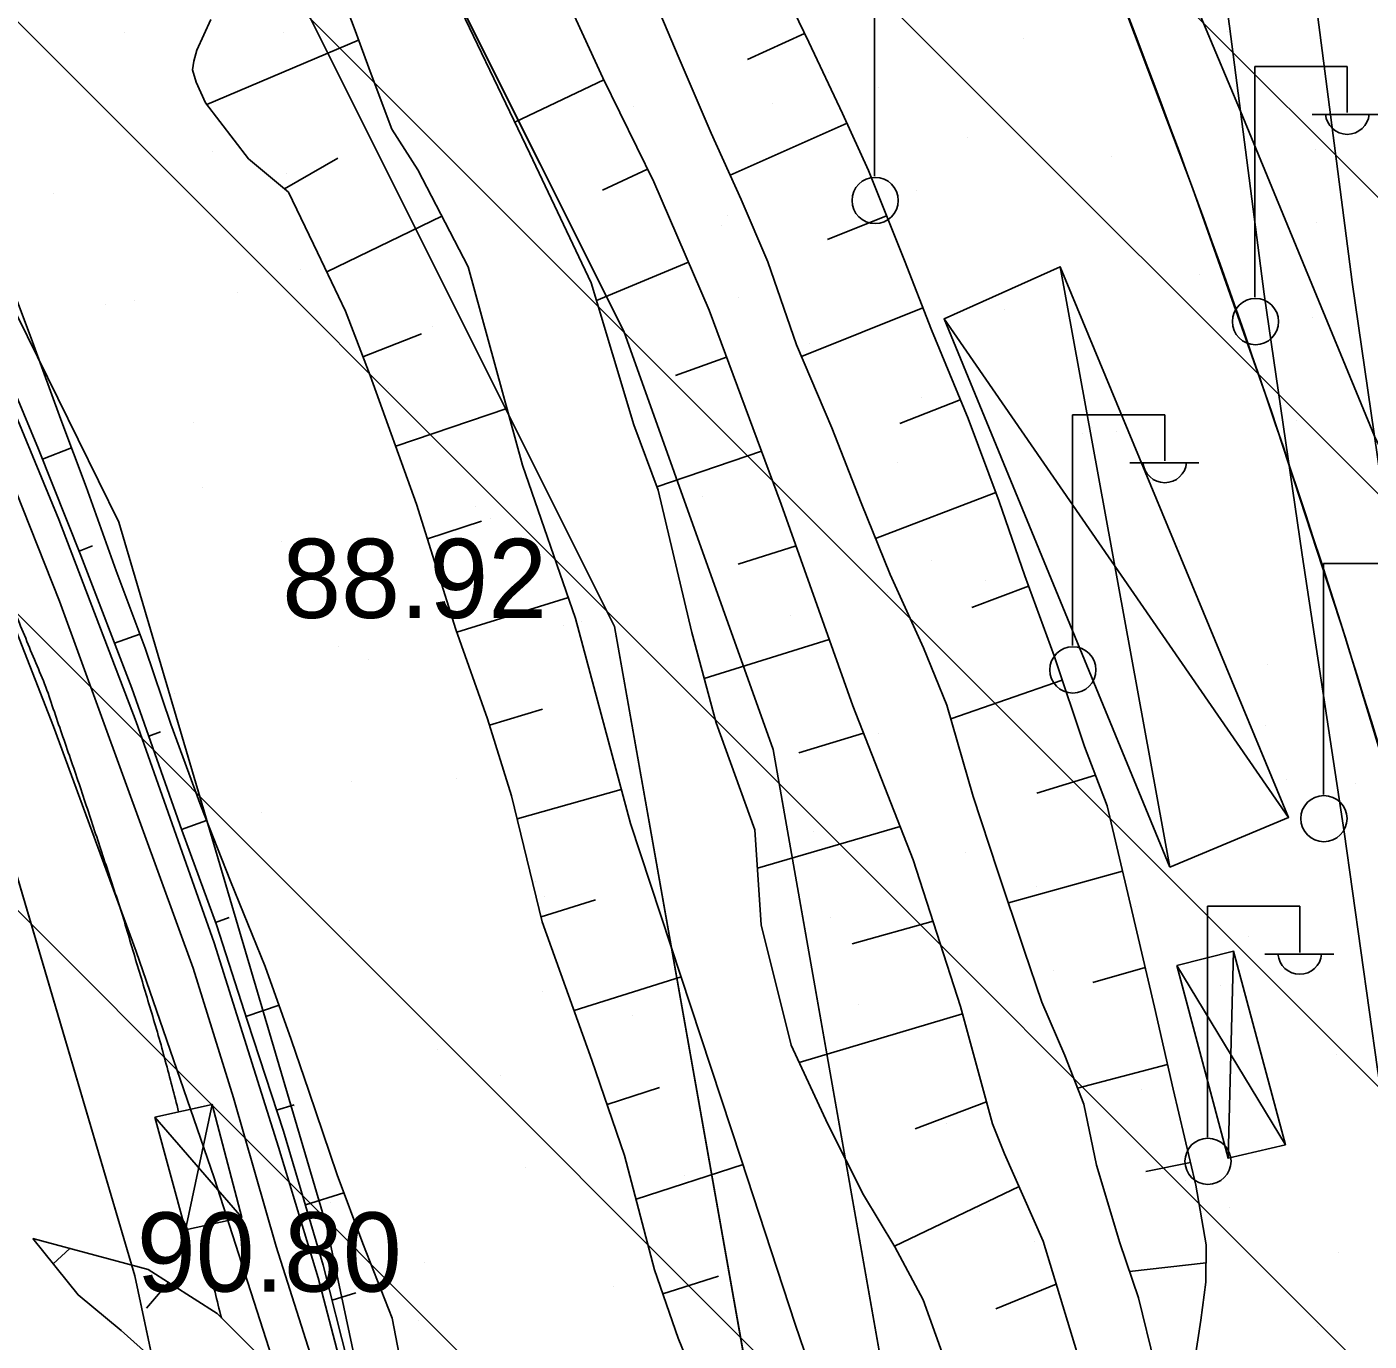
# Model space of a CAD drawing. Extents: x 417995 to 421451, y 4454518 to 4458015.
# Drawn here: x 421106.9 to 421208.7, y 4455902 to 4456001.6 of the extents above; entities that cross this region are included whole.
import ezdxf

# ---------------------------------------------------------------- set-up
doc = ezdxf.new("R2010")
doc.units = 0
for name, color, linetype in [('ADAKENARI', 7, 'Continuous'), ('B_Sundurma', 7, 'Continuous'), ('Default', 7, 'Continuous'), ('Egri_1m', 7, 'Continuous'), ('Hid_Dere_Sulu_Yat_Gen', 7, 'Continuous'), ('PL_AYA_BOLGE_PARKI', 7, 'Continuous'), ('PL_AYA_PARK_DINLENME', 7, 'Continuous'), ('PL_T_GUNUBIRLIK', 7, 'Continuous'), ('PL_TA_K_DERE', 7, 'Continuous'), ('S_Elektrik_Diregi', 7, 'Continuous'), ('Sev_Sevalti', 7, 'Continuous'), ('Sev_Sevustu', 7, 'Continuous'), ('Sev_Tarama', 7, 'Continuous'), ('Sinir_Tel_bir_taraf', 7, 'Continuous'), ('SN_TR_SIVILASMA', 7, 'Continuous'), ('TR_PARKALANI', 7, 'Continuous'), ('Y_Kot_Noktasi', 7, 'Continuous'), ('Y_Yol_Kotu', 7, 'Continuous'), ('Yol_Sose', 7, 'Continuous'), ('Yol_Toprak_Duz', 7, 'Continuous'), ('Yol_Toprak_Kesik', 7, 'Continuous')]:
    doc.layers.add(name, color=color, linetype=linetype)

# ---------------------------------------------------------------- blocks, each defined once
blk = doc.blocks.new('POINT_DISPLAY')
at = {"layer": 'Default'}
blk.add_line((0, 0), (0, 0), dxfattribs=at)

msp = doc.modelspace()

# ---------------------------------------------------------------- linework, layer by layer
at = {"layer": 'ADAKENARI'}
for p, q in [((421123.49, 4456035.93), (421152.17, 4455978.57)), ((421113.88, 4455964.09), (421080.66, 4456031.58)), ((421151.46, 4455956.18), (421128.16, 4456002.78)), ((421152.17, 4455978.57), (421163.49, 4455946.88)), ((421129.66, 4455910.66), (421113.88, 4455964.09)), ((421115.11, 4455906.97), (421099.86, 4455958.61)), ((421161.71, 4455898.39), (421151.46, 4455956.18)), ((421163.49, 4455946.88), (421172.54, 4455895.56)), ((421141.07, 4455857.05), (421129.66, 4455910.66)), ((421126.3, 4455854.38), (421115.11, 4455906.97))]:
    msp.add_line(p, q, dxfattribs=at)
msp.add_arc((420434.01, 4455711.76), 810.32, 14.95584, 31.47684, dxfattribs=at)
at = {"layer": 'B_Sundurma'}
for p, q in [((421193.56, 4455937.95), (421185.24, 4455983.45)), ((421202.55, 4455941.72), (421176.44, 4455979.5)), ((421198.38, 4455931.58), (421197.97, 4455915.89)), ((421194.09, 4455930.51), (421202.31, 4455916.92)), ((421118.95, 4455910.46), (421120.96, 4455919.97)), ((421116.61, 4455919), (421123.21, 4455911.4))]:
    msp.add_line(p, q, dxfattribs=at)
for points in [[(421193.56, 4455937.95), (421202.55, 4455941.72), (421185.24, 4455983.45), (421176.44, 4455979.5)], [(421193.56, 4455937.95), (421176.44, 4455979.5), (421185.24, 4455983.45), (421202.55, 4455941.72)], [(421194.09, 4455930.51), (421198.38, 4455931.58), (421202.31, 4455916.92), (421197.97, 4455915.89)], [(421194.09, 4455930.51), (421198.38, 4455931.58), (421202.31, 4455916.92), (421197.97, 4455915.89)], [(421116.61, 4455919), (421118.95, 4455910.46), (421123.21, 4455911.4), (421120.96, 4455919.97)], [(421116.61, 4455919), (421120.96, 4455919.97), (421123.21, 4455911.4), (421118.95, 4455910.46)]]:
    msp.add_lwpolyline(points, close=True, dxfattribs=at)
at = {"layer": 'Egri_1m'}
for points in [[(421118.42, 4455919.4), (421117.92, 4455921.34), (421117.41, 4455923.27), (421116.88, 4455925.2), (421116.31, 4455927.12), (421115.74, 4455929.03), (421115.16, 4455930.95), (421114.59, 4455932.87), (421114.01, 4455934.78), (421113.38, 4455936.68), (421112.76, 4455938.58), (421112.13, 4455940.48), (421111.5, 4455942.38), (421110.87, 4455944.28), (421110.22, 4455946.17), (421109.57, 4455948.06), (421108.92, 4455949.95), (421108.26, 4455951.84), (421107.49, 4455953.68), (421106.73, 4455955.53), (421105.96, 4455957.38), (421105.17, 4455959.22), (421104.86, 4455959.86)], [(421121.66, 4455903.8), (421121.18, 4455905.74), (421120.76, 4455907.7), (421120.48, 4455909.68), (421120.33, 4455910.77)]]:
    msp.add_spline(points, degree=3, dxfattribs=at)
at = {"layer": 'Hid_Dere_Sulu_Yat_Gen'}
for points in [[(421168.02, 4455894.88), (421165.15, 4455903.32), (421161.07, 4455915.83), (421152.67, 4455941.25), (421148.51, 4455956.81), (421144.48, 4455968.43), (421140.37, 4455983.45), (421136.54, 4455990.8), (421134.58, 4455993.87), (421133, 4455998.04), (421131.72, 4456001.56), (421127.14, 4456013.61)], [(421176.77, 4455899.81), (421174.85, 4455905.16), (421172.71, 4455909.18), (421170.32, 4455913.12), (421167.63, 4455918.48), (421164.85, 4455924.47), (421162.57, 4455933.58), (421162.1, 4455940.78), (421159.16, 4455948.89), (421157.32, 4455955.73), (421154.76, 4455966.53), (421152.91, 4455971.48), (421149.7, 4455982.23), (421145.03, 4455992.04), (421138.34, 4456006)]]:
    msp.add_lwpolyline(points, dxfattribs=at)
at = {"layer": 'PL_AYA_BOLGE_PARKI'}
msp.add_arc((420434.01, 4455711.76), 810.32, 14.95584, 31.47684, dxfattribs=at)
at = {"layer": 'PL_AYA_PARK_DINLENME'}
for points in [[(421180.89, 4455533.26), (421185.37, 4455543.12), (421189.15, 4455562.75), (421185.37, 4455581.61), (421187.64, 4455605.76), (421201.22, 4455660.85), (421206.51, 4455675.19), (421201.98, 4455705.38), (421192.17, 4455724.25), (421183.86, 4455734.81), (421185.37, 4455754.43), (421195.18, 4455786.88), (421198.96, 4455811.79), (421197.45, 4455846.5), (421189.15, 4455863.11), (421172.54, 4455895.56), (421163.49, 4455946.88), (421152.17, 4455978.57), (421123.49, 4456035.93)], [(421164.19, 4455706.15), (421157.68, 4455755.43), (421157.68, 4455755.42), (421155.11, 4455773.39), (421152.17, 4455791.3), (421148.85, 4455809.15), (421145.15, 4455826.92), (421141.09, 4455844.61), (421136.64, 4455862.22), (421131.83, 4455879.72), (421126.66, 4455897.12), (421121.11, 4455914.4), (421115.21, 4455931.57), (421108.94, 4455948.61), (421102.32, 4455965.51), (421095.34, 4455982.27), (421088.01, 4455998.87), (421080.33, 4456015.32)], [(421188.93, 4456006.25), (421195.28, 4455989.43), (421201.25, 4455972.48), (421206.84, 4455955.4), (421212.06, 4455938.2), (421216.89, 4455920.89), (421236.23, 4455848.47), (421240.3, 4455832.49), (421243.98, 4455816.42), (421247.29, 4455800.26), (421250.21, 4455784.03), (421252.74, 4455767.74), (421254.89, 4455751.39), (421256.64, 4455734.99), (421258.01, 4455718.56), (421258.99, 4455702.09)], [(421128.16, 4456002.78), (421151.46, 4455956.18), (421161.71, 4455898.39), (421179.42, 4455840.61), (421181.6, 4455782.36), (421174.05, 4455744.62), (421174.05, 4455720.47), (421186.88, 4455697.83), (421195.18, 4455678.97), (421186.13, 4455648.78), (421172.54, 4455608.78), (421170.28, 4455589.91), (421180.09, 4455564.26), (421178.58, 4455549.16), (421174.81, 4455545.39), (421170.82, 4455538.15)]]:
    msp.add_lwpolyline(points, dxfattribs=at)
at = {"layer": 'PL_T_GUNUBIRLIK'}
msp.add_lwpolyline([(421067.57, 4456024.2), (421099.86, 4455958.61), (421115.11, 4455906.97), (421126.3, 4455854.38), (421133.7, 4455804.79), (421152.1, 4455679.21), (421144.29, 4455586.77), (421139.27, 4455582.57), (421022.63, 4455660.74)], dxfattribs=at)
at = {"layer": 'PL_TA_K_DERE'}
for points in [[(421180.98, 4455533.46), (421185.37, 4455543.12), (421189.15, 4455562.75), (421185.37, 4455581.61), (421187.64, 4455605.76), (421201.22, 4455660.85), (421206.51, 4455675.19), (421201.98, 4455705.38), (421192.17, 4455724.25), (421183.86, 4455734.81), (421185.37, 4455754.43), (421195.18, 4455786.88), (421198.96, 4455811.79), (421197.45, 4455846.5), (421189.15, 4455863.11), (421172.54, 4455895.56), (421163.49, 4455946.88), (421152.17, 4455978.57), (421123.49, 4456035.93)], [(421128.16, 4456002.78), (421151.46, 4455956.18), (421161.71, 4455898.39), (421179.42, 4455840.61), (421181.6, 4455782.36), (421174.05, 4455744.62), (421174.05, 4455720.47), (421186.88, 4455697.83), (421195.18, 4455678.97), (421186.13, 4455648.78), (421172.54, 4455608.78), (421170.28, 4455589.91), (421180.09, 4455564.26), (421178.58, 4455549.16), (421174.81, 4455545.39), (421170.94, 4455538.38)]]:
    msp.add_lwpolyline(points, dxfattribs=at)
at = {"layer": 'S_Elektrik_Diregi'}
for p, q in [((421171.17, 4455990.32), (421171.17, 4456007.82)), ((421200, 4455981.14), (421200, 4455998.64)), ((421200, 4455998.64), (421207, 4455998.64)), ((421207, 4455995.14), (421207, 4455998.64)), ((421204.34, 4455995), (421209.59, 4455995)), ((421186.17, 4455954.74), (421186.17, 4455972.24)), ((421186.17, 4455972.24), (421193.17, 4455972.24)), ((421193.17, 4455968.74), (421193.17, 4455972.24)), ((421190.51, 4455968.6), (421195.76, 4455968.6)), ((421205.19, 4455943.46), (421205.19, 4455960.96)), ((421205.19, 4455960.96), (421212.19, 4455960.96)), ((421196.4, 4455917.49), (421196.4, 4455934.99)), ((421196.4, 4455934.99), (421203.4, 4455934.99)), ((421203.4, 4455931.49), (421203.4, 4455934.99)), ((421200.74, 4455931.35), (421205.99, 4455931.35))]:
    msp.add_line(p, q, dxfattribs=at)
for centre in [(421171.21, 4455988.48), (421200.04, 4455979.3), (421186.2, 4455952.9), (421205.23, 4455941.63), (421196.44, 4455915.66)]:
    msp.add_circle(centre, 1.75, dxfattribs=at)
for centre in [(421207, 4455995.15), (421193.17, 4455968.75), (421203.4, 4455931.5)]:
    msp.add_arc(centre, 1.66, 184.8384, 355.1464, dxfattribs=at)
at = {"layer": 'Sev_Sevalti'}
for points in [[(421168.02, 4455894.88), (421165.15, 4455903.32), (421161.07, 4455915.83), (421152.67, 4455941.25), (421148.51, 4455956.81), (421144.48, 4455968.43), (421140.37, 4455983.45), (421136.54, 4455990.8), (421134.58, 4455993.87), (421133, 4455998.04), (421131.72, 4456001.56), (421127.14, 4456013.61)], [(421094.71, 4456007.22), (421097.85, 4456000.22), (421100.28, 4455994.8), (421102.87, 4455988.66), (421105.09, 4455983.78), (421107.35, 4455977.77), (421109.5, 4455971.87), (421111.42, 4455966.77), (421113.69, 4455960.42), (421115.87, 4455954.56), (421117.84, 4455948.79), (421120.09, 4455942.6), (421122.34, 4455936.88), (421124.99, 4455930.42), (421126.95, 4455924.88), (421128.3, 4455920.97), (421130.44, 4455914.63), (421132.38, 4455909.42), (421134.61, 4455903.77), (421135.51, 4455899.04), (421136.14, 4455895.18), (421133.11, 4455892.83)], [(421176.77, 4455899.81), (421174.85, 4455905.16), (421172.71, 4455909.18), (421170.32, 4455913.12), (421167.63, 4455918.48), (421164.85, 4455924.47), (421162.57, 4455933.58), (421162.1, 4455940.78), (421159.16, 4455948.89), (421157.32, 4455955.73), (421154.76, 4455966.53), (421152.91, 4455971.48), (421149.7, 4455982.23), (421145.03, 4455992.04), (421138.34, 4456006)], [(421154.07, 4456004.69), (421156.37, 4455999.24), (421158.79, 4455993.59), (421161.05, 4455988.54), (421163.08, 4455983.83), (421165.25, 4455977.55), (421167.92, 4455971.26), (421170.15, 4455965.57), (421172.36, 4455960.13), (421174.87, 4455954.58), (421176.65, 4455950.24), (421178.65, 4455943.3), (421180.5, 4455937.69), (421182.52, 4455931.65), (421183.86, 4455927.73), (421185.59, 4455923.67), (421187.03, 4455919.99), (421187.98, 4455915.37), (421189.76, 4455909.48), (421191.17, 4455905.32), (421192.41, 4455900.26), (421193.25, 4455896.74), (421193.72, 4455893.32), (421194.96, 4455888.84)], [(421128.33, 4455877.13), (421127.53, 4455877.26), (421127.5, 4455879.48), (421127.03, 4455882.53), (421126.19, 4455884.83), (421125.26, 4455888.72), (421123.91, 4455891.43), (421120.86, 4455895.84), (421118.13, 4455899.21), (421114.07, 4455902.83), (421110.8, 4455905.54), (421107.37, 4455909.8)]]:
    msp.add_lwpolyline(points, dxfattribs=at)
at = {"layer": 'Sev_Sevustu'}
for points in [[(421133.11, 4455892.83), (421131.28, 4455900.31), (421129.38, 4455907.8), (421126.36, 4455917.95), (421123.63, 4455926.27), (421121.28, 4455933.59), (421118.66, 4455940.75), (421114.87, 4455951.51), (421111.01, 4455961.58), (421107.8, 4455969.63), (421104.86, 4455976.64), (421100.94, 4455984.86), (421097.31, 4455992.62), (421093.12, 4456001.22), (421089, 4456009.59)], [(421205.89, 4455803.71), (421206.29, 4455820.89), (421206.29, 4455830.68), (421205.47, 4455840.4), (421202.28, 4455854.47), (421198.13, 4455867.6), (421194.65, 4455877.38), (421192.32, 4455884.06), (421188.97, 4455893.65), (421186.51, 4455901.21), (421183.95, 4455909.6), (421181.01, 4455916.23), (421180.11, 4455918.49), (421177.68, 4455927.39), (421174.1, 4455938.52), (421169.51, 4455950.18), (421164.1, 4455965.46), (421158.62, 4455980.17), (421154.44, 4455989.88), (421150.58, 4455997.77), (421146.53, 4456006.58)], [(421194.96, 4455888.84), (421195.23, 4455899.15), (421195.89, 4455903.61), (421196.29, 4455906.49), (421196.3, 4455909.33), (421195.52, 4455913.86), (421193.8, 4455921.12), (421192.38, 4455927.34), (421190.57, 4455935.11), (421188.79, 4455942.61), (421187.09, 4455947.1), (421184.78, 4455953.98), (421182.56, 4455960.02), (421180.61, 4455965.66), (421178.26, 4455971.96), (421175.48, 4455978.67), (421173.43, 4455983.92), (421170.71, 4455990.76), (421168.75, 4455995.06), (421166.18, 4456000.47), (421163.52, 4456006.04)], [(421158.22, 4455897.48), (421156.27, 4455902.26), (421154.5, 4455907.44), (421152.22, 4455916.09), (421149.73, 4455923.32), (421145.98, 4455933.81), (421143.64, 4455943.36), (421141.83, 4455949.19), (421139.42, 4455955.97), (421136.45, 4455965.47), (421132.94, 4455975.22), (421131.07, 4455980.08), (421128.95, 4455984.54), (421126.74, 4455989.11), (421123.72, 4455991.64), (421120.45, 4455995.87), (421119.75, 4455997.45), (421119.47, 4455998.38), (421119.56, 4455999.04), (421119.8, 4455999.88), (421120.86, 4456002.19)], [(421107.37, 4455909.8), (421116.11, 4455907.45), (421121.33, 4455904.13), (421125.7, 4455899.75), (421127.55, 4455896.45), (421128.61, 4455892.51), (421129.03, 4455888.81), (421129.15, 4455885.95), (421128.96, 4455882.21), (421128.33, 4455877.13)]]:
    msp.add_lwpolyline(points, dxfattribs=at)
at = {"layer": 'Sev_Tarama'}
for p, q in [((421120.55, 4455995.74), (421132.06, 4456000.62)), ((421165.86, 4456001.14), (421161.55, 4455999.17)), ((421150.65, 4455997.62), (421143.89, 4455994.42)), ((421169.08, 4455994.33), (421160.22, 4455990.39)), ((421126.44, 4455989.36), (421130.49, 4455991.68)), ((421153.97, 4455990.85), (421150.54, 4455989.26)), ((421129.64, 4455983.08), (421138.37, 4455987.29)), ((421172.08, 4455987.32), (421167.6, 4455985.53)), ((421157.06, 4455983.81), (421150.1, 4455980.89)), ((421174.83, 4455980.35), (421165.63, 4455976.66)), ((421132.39, 4455976.64), (421136.84, 4455978.38)), ((421159.95, 4455976.61), (421156.08, 4455975.21)), ((421177.67, 4455973.38), (421173.08, 4455971.58)), ((421134.87, 4455969.87), (421143.3, 4455972.71)), ((421108.1, 4455968.87), (421110.3, 4455969.74)), ((421162.6, 4455969.49), (421154.67, 4455966.77)), ((421180.35, 4455966.35), (421171.25, 4455962.87)), ((421137.27, 4455962.84), (421141.38, 4455964.17)), ((421110.87, 4455961.91), (421111.88, 4455962.3)), ((421165.22, 4455962.31), (421160.82, 4455960.92)), ((421182.84, 4455959.26), (421178.53, 4455957.63)), ((421139.5, 4455955.75), (421147.96, 4455958.38)), ((421113.56, 4455954.92), (421115.48, 4455955.62)), ((421167.73, 4455955.21), (421158.26, 4455952.26)), ((421185.4, 4455952.12), (421176.95, 4455949.2)), ((421141.98, 4455948.71), (421146, 4455949.93)), ((421116.15, 4455947.88), (421117.04, 4455948.21)), ((421170.33, 4455948.1), (421165.43, 4455946.62)), ((421187.91, 4455944.93), (421183.46, 4455943.57)), ((421144.07, 4455941.61), (421151.97, 4455943.85)), ((421118.64, 4455940.81), (421120.53, 4455941.5)), ((421173.1, 4455941.04), (421162.29, 4455937.87)), ((421189.97, 4455937.64), (421181.32, 4455935.24)), ((421145.89, 4455934.2), (421150.02, 4455935.47)), ((421121.21, 4455933.77), (421122.26, 4455934.14)), ((421175.6, 4455933.86), (421169.48, 4455932.14)), ((421191.68, 4455930.36), (421187.71, 4455929.22)), ((421148.39, 4455927.08), (421156.51, 4455929.64)), ((421123.51, 4455926.64), (421126.03, 4455927.49)), ((421177.83, 4455926.84), (421165.46, 4455923.15)), ((421193.38, 4455922.99), (421186.56, 4455921.21)), ((421150.89, 4455919.96), (421154.87, 4455921.25)), ((421125.84, 4455919.53), (421127.17, 4455919.95)), ((421179.66, 4455920.16), (421174.25, 4455918.12)), ((421153.09, 4455912.79), (421161.21, 4455915.42)), ((421195.11, 4455915.56), (421191.72, 4455914.88)), ((421128.03, 4455912.36), (421130.95, 4455913.27)), ((421182.12, 4455913.74), (421172.68, 4455909.22)), ((421110.16, 4455909.05), (421108.91, 4455907.89)), ((421196.3, 4455907.97), (421190.5, 4455907.3)), ((421155.12, 4455905.63), (421159.33, 4455906.95)), ((421117.64, 4455906.48), (421115.98, 4455904.54)), ((421130.06, 4455905.15), (421131.85, 4455905.69)), ((421184.94, 4455906.35), (421180.35, 4455904.48))]:
    msp.add_line(p, q, dxfattribs=at)
at = {"layer": 'Sinir_Tel_bir_taraf'}
msp.add_lwpolyline([(421230.91, 4455902.6), (421225.87, 4455902.74), (421222.37, 4455918.12), (421218.87, 4455935.2), (421215.66, 4455951.02), (421213.21, 4455962.06), (421209.06, 4455970.62), (421198.91, 4455995.24), (421192.37, 4456010.82), (421184.68, 4456029.28), (421178.12, 4456045.91), (421171.29, 4456061.51), (421163.79, 4456075.27), (421155.39, 4456089.68), (421147.08, 4456103.8), (421143.47, 4456109.74)], dxfattribs=at)
at = {"layer": 'SN_TR_SIVILASMA'}
for p, q in [((421276.03, 4455922), (420004.05, 4457193.98)), ((421275.8, 4455899.78), (420015.35, 4457160.22)), ((421275.33, 4455855.34), (420037.81, 4457092.87)), ((421275.1, 4455833.12), (420049.03, 4457059.2)), ((421274.64, 4455788.69), (420075.79, 4456987.53)), ((421274.41, 4455766.47), (420135.66, 4456905.22))]:
    msp.add_line(p, q, dxfattribs=at)
at = {"layer": 'Yol_Sose'}
for points in [[(421228.15, 4455803.47), (421225.57, 4455823.33), (421221.76, 4455845.82), (421218.54, 4455866.28), (421214.57, 4455889.16), (421211.81, 4455906.6), (421209.3, 4455922.65), (421206.77, 4455940.63), (421203.57, 4455961.62), (421200.71, 4455981.38), (421198.08, 4456001.68), (421195.05, 4456023.62), (421191.88, 4456047.06), (421189.51, 4456065.97), (421187.45, 4456081.21), (421183.02, 4456108.72)], [(421234.93, 4455803.4), (421232.22, 4455824.32), (421228.39, 4455846.9), (421225.17, 4455867.38), (421221.19, 4455890.26), (421218.45, 4455907.65), (421215.94, 4455923.64), (421213.41, 4455941.61), (421210.22, 4455962.6), (421207.37, 4455982.29), (421204.74, 4456002.58), (421201.7, 4456024.53), (421198.54, 4456047.92), (421196.17, 4456066.84), (421194.09, 4456082.19), (421189.82, 4456108.77)]]:
    msp.add_lwpolyline(points, dxfattribs=at)
at = {"layer": 'Yol_Toprak_Duz'}
msp.add_lwpolyline([(421086.1, 4456009.07), (421091.58, 4455998.12), (421098.44, 4455983.71), (421102.58, 4455974.92), (421105.53, 4455967.86), (421109.39, 4455958.12), (421115.75, 4455940.63), (421119.51, 4455930.3), (421122.57, 4455920.48), (421125.81, 4455909.21), (421128.93, 4455899.43), (421129.88, 4455893.91), (421130.61, 4455888.98)], dxfattribs=at)
at = {"layer": 'Yol_Toprak_Kesik'}
msp.add_lwpolyline([(421132.88, 4455891.29), (421131.74, 4455896.16), (421130.69, 4455900.36), (421128.99, 4455906.84), (421125.98, 4455916.73), (421121.12, 4455932.23), (421115.19, 4455948.97), (421109.33, 4455964.29), (421104.07, 4455977.02), (421097.16, 4455991.64), (421093.06, 4456000.28), (421089.08, 4456008.05)], dxfattribs=at)

# ---------------------------------------------------------------- block references
at = {"layer": 'TR_PARKALANI', "xscale": 0.1, "yscale": 0.10000000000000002}
for p in [(421197.91, 4456001.32), (421114.31, 4456001.18), (421126.33, 4456001.2), (421182.44, 4456000.79), (421167.67, 4455998.18), (421171.5, 4455997.01), (421152.9, 4455995.58), (421163.46, 4455995.86), (421178.24, 4455993.26), (421120.97, 4455992.2), (421204.57, 4455992.34), (421189.1, 4455991.81), (421126.57, 4455990.53), (421174.33, 4455989.2), (421108.95, 4455989.03), (421160.01, 4455987.37), (421159.56, 4455986.6), (421204.67, 4455986.78), (421127.63, 4455983.22), (421195.77, 4455982.83), (421122.85, 4455981.5), (421160.86, 4455981.09), (421112.86, 4455980.62), (421115.07, 4455980.89), (421180.99, 4455980.22), (421204.33, 4455979.58), (421137.63, 4455978.9), (421166.22, 4455977.62), (421134.29, 4455974.25), (421174.76, 4455973.56), (421119.52, 4455971.64), (421186.95, 4455970.82), (421187.65, 4455971.24), (421189.54, 4455970.96), (421203.12, 4455971.78), (421172.88, 4455968.64), (421120.25, 4455966.73), (421158.11, 4455966.03), (421140.95, 4455965.27), (421142.02, 4455964.34), (421126.18, 4455962.66), (421194.31, 4455962.26), (421175.46, 4455961.18), (421179.54, 4455959.66), (421134.15, 4455959.2), (421172.16, 4455958.79), (421148.92, 4455956.6), (421164.77, 4455957.05), (421147.61, 4455956.29), (421130.53, 4455954.7), (421132.84, 4455953.68), (421200.97, 4455953.28), (421118.07, 4455951.08), (421186.06, 4455951.26), (421186.2, 4455950.68), (421208.64, 4455950.95), (421200.83, 4455948.66), (421171.43, 4455948.07), (421131.55, 4455944.43), (421139.5, 4455944.7), (421202.41, 4455944.62), (421207.64, 4455944.3), (421124.73, 4455942.1), (421192.86, 4455941.7), (421166.57, 4455940.66), (421178.09, 4455939.09), (421145.45, 4455936.9), (421183.46, 4455936.49), (421146.16, 4455935.72), (421167.82, 4455934.17), (421190.92, 4455934.98), (421131.39, 4455933.12), (421199.52, 4455932.72), (421184.75, 4455930.11), (421145.98, 4455928.5), (421197.36, 4455928.96), (421169.98, 4455927.51), (421152.82, 4455926.74), (421138.05, 4455924.14), (421206.18, 4455923.74), (421142.85, 4455922.13), (421191.41, 4455921.13), (421127.21, 4455919.81), (421176.64, 4455918.53), (421144.71, 4455915.16), (421156.75, 4455914.6), (421182.02, 4455914.46), (421194.76, 4455914.19), (421129.94, 4455912.55), (421179.12, 4455911.87), (421198.07, 4455912.15), (421183.3, 4455909.55), (421206.37, 4455908.78), (421137.09, 4455907.98), (421151.37, 4455906.18), (421136.6, 4455903.57), (421204.73, 4455903.17)]:
    msp.add_blockref('POINT_DISPLAY', p, dxfattribs=at)

# ---------------------------------------------------------------- texts
at = {"layer": 'Y_Kot_Noktasi'}
msp.add_text('88.92', height=6, dxfattribs=at).set_placement((421126.27, 4455956.84))
at = {"layer": 'Y_Yol_Kotu'}
msp.add_text('90.80', height=6, dxfattribs=at).set_placement((421115.25, 4455905.79))

doc.saveas('drawing.dxf')
